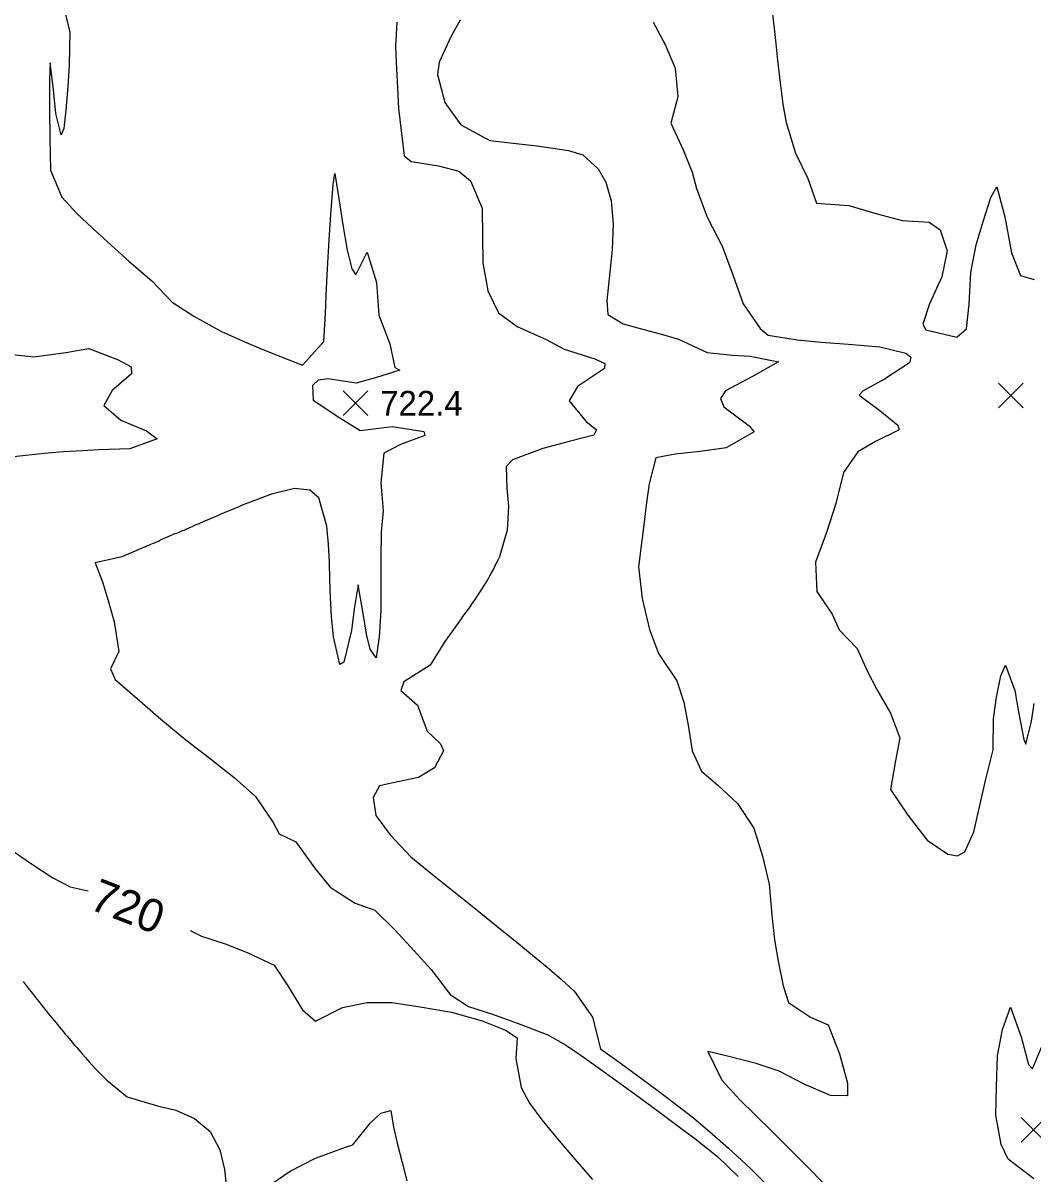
# Model space of a CAD drawing. Extents: x 2566079 to 2571326, y 424054 to 426896.
# Drawn here: x 2569490 to 2570104, y 425217 to 425917 of the extents above; entities that cross this region are included whole.
import ezdxf

# ---------------------------------------------------------------- set-up
doc = ezdxf.new("R2010")
doc.units = 0
for name, color, linetype in [('Contour_ADS_Label_Major', 7, 'Continuous'), ('Contour_ADS_Major', 7, 'Continuous'), ('Contour_ADS_Minor', 7, 'Continuous'), ('Contour_ADS_Spot_Elevation', 7, 'Continuous')]:
    doc.layers.add(name, color=color, linetype=linetype)

# ---------------------------------------------------------------- blocks, each defined once
blk = doc.blocks.new('S750')
at = {"layer": 'Contour_ADS_Spot_Elevation'}
for p, q in [((-0.5, 0.498), (0.5, -0.498)), ((-0.498, -0.5), (0.498, 0.5))]:
    blk.add_line(p, q, dxfattribs=at)

msp = doc.modelspace()

# ---------------------------------------------------------------- linework, layer by layer
at = {"layer": 'Contour_ADS_Major'}
for points in [[(2569945.45, 425924.57), (2569947.61, 425906.62), (2569948.85, 425894.3), (2569950.34, 425880.84), (2569952.09, 425867.85), (2569954.16, 425856.58), (2569959.81, 425838.03), (2569967.23, 425822.55), (2569972.6, 425807.48), (2569992.23, 425806.1), (2570009.49, 425801.13), (2570024.69, 425796.93), (2570041.06, 425795.93), (2570047.82, 425791.25), (2570052.11, 425778.59), (2570048.69, 425762.66), (2570041.24, 425746.38), (2570037.3, 425733.84), (2570039.06, 425730.54), (2570057.97, 425725.94), (2570063.84, 425731.04), (2570065.42, 425746.17), (2570066.5, 425765.31), (2570069.61, 425782.18), (2570074.01, 425796.4), (2570078.55, 425811.07), (2570082.21, 425817.54), (2570087.2, 425799.15), (2570089.06, 425788.19), (2570091.18, 425777.36), (2570096.58, 425763.58), (2570105.01, 425761.12)], [(2569478.13, 425716.08), (2569496.25, 425714.01), (2569515.83, 425716.71), (2569529.79, 425719.15), (2569547.13, 425712.33), (2569555.43, 425707.88), (2569555.78, 425703.77), (2569543.93, 425693.57), (2569538.96, 425684.34), (2569549.2, 425675.54), (2569564.78, 425668.94)], [(2569564.78, 425668.94), (2569571.28, 425664.18), (2569554.66, 425658.11), (2569535.62, 425657.35), (2569526, 425656.87), (2569514.32, 425656.12), (2569502.65, 425655.21), (2569484.19, 425653.26)], [(2569479.05, 425416.5), (2569494.2, 425405.82), (2569507.85, 425397.04), (2569518.34, 425391.45), (2569529.31, 425389.02)], [(2569591.51, 425365.02), (2569598.26, 425361.41), (2569612.7, 425356.73), (2569626.03, 425351.61), (2569642.63, 425343.84), (2569650.93, 425331.35), (2569659.68, 425316.57), (2569667.68, 425309.76), (2569684.02, 425318.11), (2569699.21, 425321.03), (2569714.08, 425321.09), (2569731.28, 425318.47), (2569750.48, 425315.26), (2569769.14, 425310.03), (2569783.33, 425304.24), (2569790.46, 425299.7), (2569789.57, 425287.07), (2569792.77, 425269.43), (2569797.89, 425259.84), (2569805.35, 425249.66), (2569814.75, 425238.33), (2569825.49, 425225.71), (2569836.28, 425213.35)]]:
    msp.add_lwpolyline(points, dxfattribs=at)
at = {"layer": 'Contour_ADS_Minor'}
msp.add_line((2569582.58, 425606.43), (2569573.26, 425602.44), dxfattribs=at)
for points in [[(2569513.52, 425930.61), (2569518.25, 425911.56), (2569517.87, 425891.8), (2569516.99, 425878.59), (2569515.85, 425864.14), (2569514.49, 425853.07), (2569512.95, 425849.11), (2569509.67, 425862.17), (2569508.17, 425876.57), (2569506.16, 425892.99), (2569505.88, 425882.88), (2569505.93, 425864.74), (2569506.04, 425847), (2569506.54, 425827.59), (2569513.41, 425811.1), (2569522.45, 425801.2), (2569531.78, 425792.59), (2569543.27, 425782.05), (2569554.2, 425772.22), (2569568.08, 425760.36), (2569580.48, 425747.31), (2569593.69, 425738.81), (2569610.46, 425729.41), (2569625.07, 425722.88), (2569634.67, 425718.9), (2569650.36, 425712.6), (2569659.87, 425709.01), (2569672.82, 425723.44), (2569673.69, 425740.45), (2569674.14, 425751.6), (2569674.99, 425767.63), (2569676.04, 425785.33), (2569677.01, 425800.55), (2569678.44, 425818.96), (2569679.38, 425825.68), (2569682.08, 425808.94), (2569684.32, 425794.31), (2569687.04, 425778.88), (2569689.79, 425767.58), (2569692.22, 425763.97), (2569699.03, 425777.69), (2569704.83, 425759.2), (2569706.27, 425739.37), (2569712.81, 425722.02), (2569715.98, 425707.62), (2569718.98, 425705.88), (2569704.7, 425701.48), (2569692.38, 425698.09), (2569675.13, 425700.61), (2569669.35, 425699.75), (2569665.76, 425696.58), (2569666.32, 425687.62), (2569682.56, 425676.87), (2569694.93, 425669.17), (2569714.36, 425671.61), (2569733.68, 425668.6), (2569734.15, 425666.18), (2569719.41, 425660.73), (2569709.19, 425655.49), (2569707.51, 425637.32), (2569708.81, 425620.3), (2569707.63, 425607.25), (2569707.44, 425592.07), (2569707.44, 425574.53), (2569707.43, 425559.71), (2569706.35, 425543.6), (2569704.62, 425530.93), (2569700.91, 425536.2), (2569698.76, 425545.21), (2569696.78, 425557.79), (2569693.62, 425575.33), (2569691.21, 425560.64), (2569689.63, 425547.42), (2569684.94, 425528.24), (2569682.45, 425526.82), (2569678.61, 425543.58), (2569677.43, 425556.07), (2569676.75, 425567.6), (2569676.4, 425578.27), (2569676.11, 425588.91), (2569675.63, 425600.01)], [(2569717.08, 425917.75), (2569716.4, 425902.97), (2569716.78, 425893.19), (2569717.3, 425881.88), (2569718.26, 425865.25), (2569720.35, 425846.77), (2569721.57, 425836.41), (2569725.82, 425832.89), (2569742.62, 425830.25), (2569754.84, 425826.99), (2569761.9, 425821.07), (2569769.08, 425804.49), (2569769.28, 425787.27), (2569769.56, 425771.17), (2569772.64, 425754.14), (2569778.94, 425740.74), (2569790.37, 425732.44), (2569808.04, 425724.56), (2569819.08, 425718.65), (2569837.73, 425712.9), (2569843.65, 425709.98), (2569843.54, 425706.91), (2569827.11, 425696.01), (2569821.98, 425687.33), (2569832.26, 425674.9), (2569838.58, 425669.67), (2569837.01, 425666.42), (2569821.95, 425662.47), (2569806.06, 425658.33), (2569787.6, 425651.42), (2569783.62, 425647.36), (2569784.08, 425634.13), (2569785.19, 425622.91), (2569784.3, 425608.59), (2569779.36, 425591.72)], [(2569755.74, 425918.92), (2569750.27, 425909.15), (2569742.89, 425893.44), (2569741.93, 425885.88), (2569746.41, 425868.82), (2569756.14, 425855.12), (2569773.82, 425845.78), (2569786.19, 425844.28), (2569802.56, 425842.39), (2569821.54, 425839.57), (2569830.3, 425837), (2569839.76, 425828.45), (2569844.44, 425820.32), (2569847.68, 425809.03), (2569848.71, 425794.69), (2569848.11, 425779.34), (2569846.82, 425765.56), (2569844.9, 425748.26), (2569845.65, 425739.82), (2569854.93, 425734.21), (2569865.21, 425731.22), (2569877.33, 425728), (2569888.5, 425724.7), (2569905.9, 425716.76), (2569921.49, 425715.1), (2569932.21, 425714.34), (2569949.45, 425711.09), (2569933.13, 425701.8), (2569917.1, 425693.38), (2569914.05, 425688.63), (2569916.04, 425683.67), (2569931.57, 425672.01), (2569934.62, 425668.31), (2569917.65, 425658.7), (2569901.79, 425656.34), (2569886.56, 425654.86), (2569874.85, 425652.65), (2569870.71, 425636.83), (2569869.18, 425625.44), (2569867.64, 425613.38), (2569866.17, 425602.33), (2569864.14, 425586.33), (2569866.51, 425567), (2569870.96, 425548.17), (2569876.44, 425533.44), (2569887.47, 425516.92), (2569891.76, 425503.91), (2569894.34, 425489.82), (2569896.88, 425474.36), (2569902.59, 425461.9), (2569912.44, 425453.41), (2569924.46, 425442.26), (2569934.44, 425427.21), (2569939.61, 425410.22), (2569943.72, 425393.13), (2569945.31, 425374.19), (2569946.98, 425359.26), (2569949.24, 425346.23), (2569952.27, 425331.18), (2569955.55, 425321.1), (2569968.93, 425312.18), (2569979.56, 425307.43), (2569986.51, 425289.97), (2569991.37, 425272.02), (2569991.39, 425264.25), (2569981.09, 425264.47), (2569965, 425271.34), (2569949.76, 425279.38), (2569935.83, 425283.9), (2569918.43, 425288.48), (2569906.49, 425291.27), (2569914.93, 425273.83), (2569926.12, 425261.76), (2569935.06, 425252.91), (2569945.92, 425242.13), (2569956.07, 425232.05), (2569968.98, 425219.14), (2569979.4, 425208.36)], [(2569873.13, 425917.74), (2569880.37, 425904.06), (2569886.6, 425889.7), (2569888.23, 425872.26), (2569883.8, 425856.27), (2569891.39, 425839.93), (2569896.81, 425826.37), (2569899.5, 425816.52), (2569905.95, 425798.96), (2569915.13, 425781.36), (2569921.52, 425764.02), (2569927.94, 425746.36), (2569938.19, 425731.35), (2569943.17, 425727.2), (2569960.7, 425724.31), (2569975.32, 425723.01), (2569992.01, 425721.79), (2570011.05, 425720.05), (2570026.82, 425716.26), (2570029.91, 425713.87), (2570029.08, 425710.34), (2570013.99, 425700.48), (2570000.95, 425693.3), (2569998.41, 425690.79), (2570010.98, 425681.39), (2570022.02, 425672.52), (2570022.87, 425669.6), (2570008.48, 425662.61), (2569997.59, 425656.14), (2569989.05, 425643.74), (2569984.19, 425624.7), (2569978.64, 425607.07), (2569972, 425589.14), (2569972.7, 425571.24), (2569982.01, 425557.42), (2569986.39, 425547.92), (2569997.28, 425536.46), (2570003.36, 425522.87), (2570009.33, 425511.67), (2570017.64, 425497.2), (2570023.3, 425482.23), (2570020.38, 425467.19), (2570017.46, 425450.71), (2570028.02, 425435.12), (2570039.92, 425419.83), (2570052.39, 425411.35), (2570058.34, 425410.36), (2570062.81, 425412.76), (2570068.29, 425424.91), (2570071.94, 425441.02), (2570075.63, 425457.01), (2570080.06, 425474.87), (2570080.23, 425493.65), (2570082.02, 425507.02), (2570084.62, 425519.99), (2570087.58, 425526.49), (2570093.19, 425511.05), (2570095.48, 425498), (2570098.68, 425481.09), (2570099.83, 425478.27), (2570103.25, 425492.24), (2570104.91, 425503.07)], [(2569675.63, 425600.01), (2569674.66, 425610.91), (2569669.8, 425628.31), (2569664.25, 425632.99), (2569654.89, 425633.84), (2569640.83, 425630.39), (2569623.07, 425623.7)], [(2569563.94, 425598.45), (2569549.82, 425592.42), (2569533.53, 425588.65), (2569537.98, 425577.15), (2569541.59, 425565.76), (2569545.18, 425552.71), (2569548.08, 425534.77), (2569542.91, 425524.19), (2569545.71, 425517.73), (2569559.15, 425506.18), (2569573.54, 425493.6), (2569588.85, 425480.97), (2569602.77, 425470.27), (2569618.21, 425458.01), (2569631.15, 425446.42), (2569642.02, 425430.72), (2569645.59, 425423.74), (2569655.73, 425418.89), (2569666.99, 425403.14), (2569676.58, 425391.33), (2569691.91, 425381.66), (2569703.8, 425377.24), (2569715.99, 425365.41), (2569727.65, 425352.59), (2569738.11, 425341.1), (2569749.65, 425326), (2569760.81, 425318.78), (2569775.38, 425314.08), (2569792.69, 425307.64), (2569808.98, 425301.35), (2569819.81, 425295.33), (2569827.95, 425289.81), (2569839.13, 425281.89), (2569851.48, 425273), (2569862.44, 425265.04), (2569876.19, 425254.95), (2569890, 425244.66), (2569898.47, 425238.28), (2569912.19, 425227.49), (2569924.77, 425215.17)], [(2569757, 425555.35), (2569746.43, 425540.83), (2569737.51, 425526.47), (2569721.33, 425516.21), (2569719.69, 425510.95), (2569729.75, 425502.07), (2569735.69, 425486.27), (2569743.64, 425478.54), (2569745.6, 425474.29), (2569740.01, 425463.98), (2569730.27, 425457.94), (2569713.93, 425454.57), (2569706.69, 425452.93), (2569702.82, 425445.94), (2569704.43, 425434.93), (2569713.19, 425423.19), (2569725.79, 425409.85), (2569738.85, 425398.91), (2569744.95, 425394.09), (2569754.84, 425386.21), (2569767.01, 425376.46), (2569779.33, 425366.55), (2569790.16, 425357.79), (2569799.69, 425350.02), (2569808.58, 425342.68), (2569817.24, 425335.32), (2569825.2, 425327.78), (2569836.29, 425312.14), (2569841.1, 425292.98), (2569853.86, 425283.79), (2569863.72, 425276.47), (2569875.28, 425267.88), (2569885.59, 425260.22), (2569897.62, 425251.03), (2569910.7, 425239.75), (2569918.99, 425232.39), (2569932.31, 425220.19), (2569946.14, 425206.23)], [(2570104.72, 425213.76), (2570089.19, 425225.87), (2570084.91, 425234.69), (2570084.91, 425234.69), (2570081.74, 425252.49), (2570082.07, 425269.96), (2570082.68, 425288.74), (2570085.62, 425304.71), (2570090.62, 425318.27), (2570097.11, 425300.28), (2570101.5, 425283.39), (2570103.96, 425280.65), (2570111.1, 425297.81)], [(2569540.67, 425273.77), (2569553.02, 425263.66), (2569571.52, 425258.18), (2569582.62, 425255.51), (2569594.13, 425250.53), (2569603.67, 425242.58), (2569609.47, 425231.54), (2569612.28, 425219.54), (2569614.07, 425202.56)], [(2569636.3, 425207.53), (2569652.25, 425218.56), (2569667.76, 425226.32), (2569685.85, 425233.04), (2569690.49, 425234.53), (2569701.14, 425247.94), (2569707.43, 425253.79), (2569713.45, 425255.32), (2569715.13, 425245.3), (2569717.44, 425235.51), (2569720.38, 425223.7), (2569723.26, 425212.59)]]:
    msp.add_lwpolyline(points, dxfattribs=at)
for centre, radius, start, end in [((2570563.64, 423375.66), 2436.87, 112.70427, 113.2142), ((2559186.77, 449806.75), 26338.72, 293.247072, 293.271367), ((2571319.41, 421598.96), 4367.64, 113.13884, 113.28529), ((2563595.55, 439552.54), 15176.9, 293.157192, 293.195464), ((2569644.94, 425652.81), 147.66, 327.37193, 335.55899), ((2569374, 425832.21), 472.59, 324.13814, 326.76584), ((2570507.62, 426127.73), 1290.89, 217.95165, 219.04966), ((2570178.13, 425856.48), 864.12, 218.84541, 220.76065), ((2569786.7, 425517.53), 346.34, 220.56695, 224.7335)]:
    msp.add_arc(centre, radius, start, end, dxfattribs=at)

# ---------------------------------------------------------------- block references
at = {"layer": 'Contour_ADS_Spot_Elevation', "xscale": 15, "yscale": 15}
for p in [(2570090.76, 425690.55), (2569692.04, 425685.81), (2570104.5, 425243.62)]:
    msp.add_blockref('S750', p, dxfattribs=at)

# ---------------------------------------------------------------- texts
at = {"layer": 'Contour_ADS_Label_Major'}
msp.add_text('720', height=20, rotation=338.89722, dxfattribs=at).set_placement((2569529.08, 425378.39))
at = {"layer": 'Contour_ADS_Spot_Elevation'}
msp.add_text('722.4', height=15, dxfattribs=at).set_placement((2569707.04, 425678.31))

doc.saveas('drawing.dxf')
